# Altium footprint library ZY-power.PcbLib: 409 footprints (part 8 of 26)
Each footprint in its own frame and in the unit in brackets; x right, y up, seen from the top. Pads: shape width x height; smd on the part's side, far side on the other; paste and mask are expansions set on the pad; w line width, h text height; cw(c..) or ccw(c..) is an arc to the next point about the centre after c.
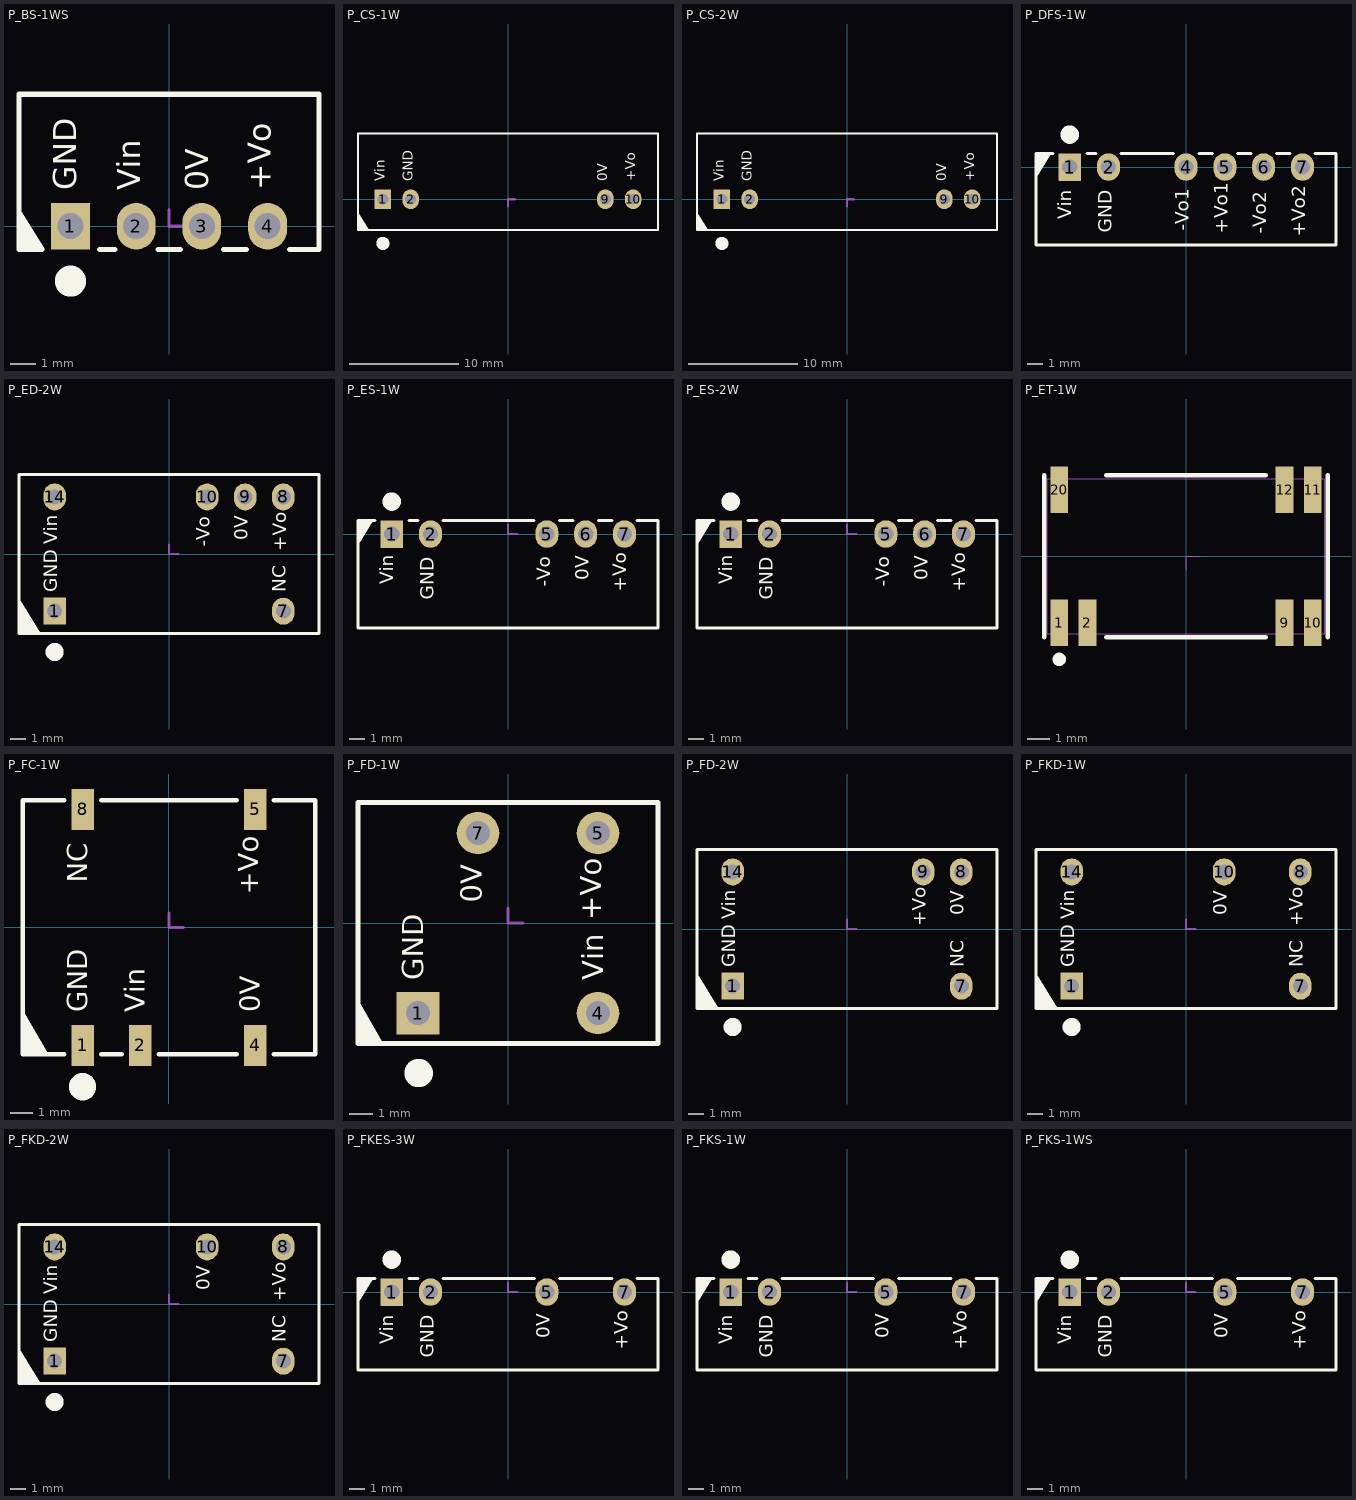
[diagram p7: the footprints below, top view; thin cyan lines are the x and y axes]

## P_BS-1WS [mm]
height 10.16
pads (4):
  rect 1.5x1.8 hole 1: 1(-3.81,0)
  oval 1.5x1.8 hole 1: 2(-1.27,0) 3(1.27,0) 4(3.81,0)
Top Overlay:
  circle w1: c-3.81,-2.125 r0.1
  region: -5.8,0.686 -5.8,-0.889 -4.813,-0.889
  lines w0.2: -4.91,-0.9 -5.8,-0.9 -5.8,5.1 5.8,5.1 5.8,-0.9 4.656,-0.9 ; -2.69,-0.9 -2.09,-0.9 ; -0.424,-0.9 0.45,-0.9 ; 2.116,-0.9 2.99,-0.9
  text "+Vo" at 4.216,1.396 h1.52
  text "0V" at 1.803,1.396 h1.52
  text "Vin" at -0.813,1.397 h1.52
  text "GND" at -3.302,1.396 h1.52
Mechanical 15:
  lines w0.127: 0,0.635 0,0 0.635,0
3D body "zhenjao01.stp": height 8.36, standoff -4.08, extent -4.51,-0.12 -3.11,1.48
3D body: height 10.16, standoff 0, extent -5.8,-0.9 5.8,5.1
3D body "zhenjao01.stp": height 8.36, standoff -4.08, extent -1.97,-0.12 -0.57,1.48
3D body "zhenjao01.stp": height 8.36, standoff -4.08, extent 0.57,-0.12 1.97,1.48
3D body "zhenjao01.stp": height 8.36, standoff -4.08, extent 3.11,-0.12 4.51,1.48

## P_CS-1W [mm]
height 11.4
pads (4):
  rect 1.5x1.8 hole 1: 1(-11.43,0)
  oval 1.5x1.8 hole 1: 2(-8.89,0) 9(8.89,0) 10(11.43,0)
Top Overlay:
  circle w1: c-11.43,-4.025 r0.1
  region: -13.7,-1.214 -13.7,-2.8 -12.706,-2.8
  lines w0.2: -13.7,-2.8 -13.7,6 13.7,6 13.7,-2.8 -13.7,-2.8
  text "+Vo" at 11.925,1.625 h1.52
  text "0V" at 9.385,1.625 h1.52
  text "GND" at -8.395,1.625 h1.52
  text "Vin" at -10.935,1.626 h1.52
Mechanical 15:
  lines w0.203: 0,-0.635 0,0 0.635,0
3D body "zhenjao01.stp": height 8.36, standoff -4.08, extent -9.59,-0.12 -8.19,1.48
3D body "zhenjao01.stp": height 8.36, standoff -4.08, extent -12.13,-0.12 -10.73,1.48
3D body "zhenjao01.stp": height 8.36, standoff -4.08, extent 8.19,-0.12 9.59,1.48
3D body "zhenjao01.stp": height 8.36, standoff -4.08, extent 10.73,-0.12 12.13,1.48
3D body: height 10.1, standoff 0, extent -13.7,-2.8 13.7,6

## P_CS-2W [mm]
height 11.5
pads (4):
  rect 1.5x1.8 hole 1: 1(-11.43,0)
  oval 1.5x1.8 hole 1: 2(-8.89,0) 9(8.89,0) 10(11.43,0)
Top Overlay:
  circle w1: c-11.43,-4.025 r0.1
  region: -13.7,-1.214 -13.7,-2.8 -12.706,-2.8
  lines w0.2: -13.7,-2.8 13.7,-2.8 13.7,6 -13.7,6 -13.7,-2.8
  text "Vin" at -10.935,1.626 h1.52
  text "GND" at -8.395,1.625 h1.52
  text "0V" at 9.385,1.625 h1.52
  text "+Vo" at 11.925,1.625 h1.52
Mechanical 15:
  lines w0.203: 0,-0.635 0,0 0.635,0
3D body "zhenjao01.stp": height 8.36, standoff -4.08, extent -9.59,-0.12 -8.19,1.48
3D body "zhenjao01.stp": height 8.36, standoff -4.08, extent -12.13,-0.12 -10.73,1.48
3D body "zhenjao01.stp": height 8.36, standoff -4.08, extent 8.19,-0.12 9.59,1.48
3D body "zhenjao01.stp": height 8.36, standoff -4.08, extent 10.73,-0.12 12.13,1.48
3D body: height 10.1, standoff 0, extent -13.7,-2.8 13.7,6

## P_DFS-1W [mm]
height 10.16
pads (6):
  rect 1.5x1.8 hole 1: 1(-7.62,0)
  oval 1.5x1.8 hole 1: 2(-5.08,0) 4(0,0) 5(2.54,0) 6(5.08,0) 7(7.62,0)
Top Overlay:
  circle w1: c-7.62,2.125 r0.1
  region: -9.83,-0.686 -9.83,0.9 -8.836,0.9
  lines w0.2: -8.72,0.9 -9.83,0.9 -9.83,-5.1 9.82,-5.1 9.82,0.9 8.44,0.9 ; -6.5,0.9 -5.9,0.9 ; -4.26,0.9 -0.82,0.9 ; 0.846,0.9 1.72,0.9 ; 3.386,0.9 4.26,0.9 ; 5.926,0.9 6.8,0.9
  text "-Vo1" at 0.478,-4.176 h1.52
  text "+Vo1" at 3.018,-4.377 h1.52
  text "-Vo2" at 5.558,-4.356 h1.52
  text "+Vo2" at 8.098,-4.556 h1.52
  text "GND" at -4.572,-4.318 h1.52
  text "Vin" at -7.239,-3.435 h1.52
Mechanical 15:
  lines w0.127: 0,0.635 0,0 0.635,0
3D body "zhenjao01.stp": height 8.36, standoff -4.08, extent 4.38,-1.48 5.78,0.12
3D body "zhenjao01.stp": height 8.36, standoff -4.08, extent -0.7,-1.48 0.7,0.12
3D body: height 10.16, standoff 0, extent -9.83,-5.1 9.82,0.9
3D body "zhenjao01.stp": height 8.36, standoff -4.08, extent 6.92,-1.48 8.32,0.12
3D body "zhenjao01.stp": height 8.36, standoff -4.08, extent 1.84,-1.48 3.24,0.12
3D body "zhenjao01.stp": height 8.36, standoff -4.08, extent -5.78,-1.48 -4.38,0.12
3D body "zhenjao01.stp": height 8.36, standoff -4.08, extent -8.32,-1.48 -6.92,0.12

## P_ED-2W [mm]
height 8.5
pads (6):
  rect 1.5x1.8 hole 1: 1(-7.62,-3.81)
  oval 1.5x1.8 hole 1: 7(7.62,-3.81) 8(7.62,3.81) 9(5.08,3.81) 10(2.54,3.81) 14(-7.62,3.81)
Top Overlay:
  circle w1: c-7.62,-6.525 r0.1
  region: -10,-2.97 -10,-5.3 -8.54,-5.3
  lines w0.2: -10,-5.3 10,-5.3 10,5.3 -10,5.3 -10,-5.3
  text "-Vo" at 3.023,0.487 h1.52
  text "+Vo" at 8.103,0.177 h1.52
  text "0V" at 5.542,0.916 h1.52
  text "GND" at -7.138,-2.557 h1.52
  text "NC" at 8.082,-2.557 h1.52
  text "Vin" at -7.138,0.645 h1.52
Mechanical 15:
  lines w0.127: 0,0.635 0,0 0.635,0
3D body: height 0, standoff -4.91, extent 2.317,3.586 2.765,4.035
3D body: height 0, standoff -4.91, extent 7.397,3.586 7.845,4.035
3D body: height 0, standoff -4.91, extent 7.397,-4.034 7.845,-3.585
3D body: height 0, standoff -4.91, extent -7.843,3.586 -7.395,4.035
3D body: height 0, standoff -4.91, extent -7.843,-4.034 -7.395,-3.585
3D body: height 8.5, standoff 0, extent -10,-5.3 10,5.3
3D body: height 0, standoff -4.91, extent 4.857,3.586 5.305,4.035

## P_ES-1W [mm]
height 10.16
pads (5):
  rect 1.5x1.8 hole 1: 1(-7.62,0)
  oval 1.5x1.8 hole 1: 2(-5.08,0) 5(2.54,0) 6(5.08,0) 7(7.62,0)
Top Overlay:
  circle w1: c-7.62,2.125 r0.1
  region: -9.83,-0.686 -9.83,0.9 -8.836,0.9
  lines w0.2: -8.72,0.9 -9.83,0.9 -9.83,-6.15 9.82,-6.15 9.82,0.9 8.44,0.9 ; -6.5,0.9 -5.9,0.9 ; -4.26,0.9 1.694,0.9 ; 3.386,0.9 4.26,0.9 ; 5.926,0.9 6.8,0.9
  text "0V" at 5.588,-3.034 h1.52
  text "Vin" at -7.239,-3.304 h1.52
  text "GND" at -4.572,-4.318 h1.52
  text "-Vo" at 3.048,-3.462 h1.52
  text "+Vo" at 8.031,-3.772 h1.52
Mechanical 15:
  lines w0.127: 0,0.635 0,0 0.635,0
3D body: height 10.1, standoff 0, extent -9.83,-6.15 9.82,0.9
3D body "zhenjao01.stp": height 8.36, standoff -4.08, extent -8.32,-1.48 -6.92,0.12
3D body "zhenjao01.stp": height 8.36, standoff -4.08, extent -5.78,-1.48 -4.38,0.12
3D body "zhenjao01.stp": height 8.36, standoff -4.08, extent 1.84,-1.48 3.24,0.12
3D body "zhenjao01.stp": height 8.36, standoff -4.08, extent 4.38,-1.48 5.78,0.12
3D body "zhenjao01.stp": height 8.36, standoff -4.08, extent 6.92,-1.48 8.32,0.12

## P_ES-2W [mm]
height 10.16
pads (5):
  rect 1.5x1.8 hole 1: 1(-7.62,0)
  oval 1.5x1.8 hole 1: 2(-5.08,0) 5(2.54,0) 6(5.08,0) 7(7.62,0)
Top Overlay:
  circle w1: c-7.62,2.125 r0.1
  region: -9.83,-0.686 -9.83,0.9 -8.836,0.9
  lines w0.2: -8.72,0.9 -9.83,0.9 -9.83,-6.15 9.82,-6.15 9.82,0.9 8.44,0.9 ; -6.5,0.9 -5.9,0.9 ; -4.26,0.9 1.694,0.9 ; 3.386,0.9 4.26,0.9 ; 5.926,0.9 6.8,0.9
  text "+Vo" at 8.031,-3.772 h1.52
  text "-Vo" at 3.048,-3.462 h1.52
  text "GND" at -4.572,-4.318 h1.52
  text "Vin" at -7.239,-3.304 h1.52
  text "0V" at 5.588,-3.034 h1.52
Mechanical 15:
  lines w0.127: 0,0.635 0,0 0.635,0
3D body "zhenjao01.stp": height 8.36, standoff -4.08, extent 6.92,-1.48 8.32,0.12
3D body "zhenjao01.stp": height 8.36, standoff -4.08, extent 4.38,-1.48 5.78,0.12
3D body "zhenjao01.stp": height 8.36, standoff -4.08, extent 1.84,-1.48 3.24,0.12
3D body "zhenjao01.stp": height 8.36, standoff -4.08, extent -5.78,-1.48 -4.38,0.12
3D body "zhenjao01.stp": height 8.36, standoff -4.08, extent -8.32,-1.48 -6.92,0.12
3D body: height 10.1, standoff 0, extent -9.83,-6.15 9.82,0.9

## P_ET-1W [mm]
height 3
pads (7):
  rect 0.8x2.1 smd: 1(-5.715,-3) 2(-4.445,-3) 9(4.445,-3) 10(5.715,-3) 11(5.715,3) 12(4.445,3) 20(-5.715,3)
Top Overlay:
  circle w0.4: c-5.715,-4.649 r0.1
  lines w0.2: -6.4,-3.65 -6.4,3.65 ; -3.6,-3.65 3.6,-3.65 ; -3.6,3.65 3.6,3.65 ; 6.4,-3.65 6.4,3.65
Mechanical 13:
  lines w0.05: -6.25,-3.5 6.25,-3.5 6.25,3.5 -6.25,3.5 -6.25,-3.5
Mechanical 15:
  lines w0.05: 0,-0.635 0,0 0.635,0

## P_FC-1W [mm]
height 7.14
pads (5):
  rect 1x1.8 smd: 1(-3.81,-5.203) 2(-1.27,-5.203) 4(3.81,-5.203) 5(3.81,5.203) 8(-3.81,5.203)
Top Overlay:
  circle w1: c-3.812,-7.026 r0.1
  region: -5.334,-5.6 -6.45,-3.661 -6.45,-5.6
  lines w0.2: -4.623,-5.6 -6.45,-5.6 -6.45,5.6 -4.623,5.6 ; -2.997,-5.6 -2.084,-5.6 ; -2.997,5.6 2.997,5.6 ; -0.456,-5.6 2.997,-5.6 ; 4.623,-5.6 6.45,-5.6 6.45,5.6 4.623,5.6
  text "NC" at -3.302,1.972 h1.52
  text "Vin" at -0.762,-3.739 h1.52
  text "+Vo" at 4.244,1.443 h1.52
  text "0V" at 4.318,-3.741 h1.52
  text "GND" at -3.302,-3.741 h1.52
Mechanical 15:
  lines w0.127: 0,0.635 0,0 0.635,0

## P_FD-1W [mm]
height 8.1
pads (4):
  rect 1.8x1.8 hole 1: 1(-3.81,-3.81)
  round 1.8 hole 1: 4(3.81,-3.81) 5(3.81,3.81) 7(-1.27,3.81)
Top Overlay:
  circle w1: c-3.783,-6.35 r0.1
  region: -5.234,-5.2 -6.35,-3.261 -6.35,-5.2
  lines w0.2: -6.35,-5.1 6.35,-5.1 6.35,5.1 -6.35,5.1 -6.35,-5.1
  text "GND" at -3.302,-2.413 h1.52
  text "Vin" at 4.318,-2.413 h1.52
  text "+Vo" at 4.244,0.127 h1.52
  text "0V" at -0.813,0.864 h1.52
Mechanical 15:
  lines w0.127: 0,0.635 0,0 0.635,0
3D body: height 0, standoff -4.91, extent -4.033,-4.034 -3.585,-3.585
3D body: height 0, standoff -4.91, extent 3.587,-4.034 4.035,-3.585
3D body: height 0, standoff -4.91, extent 3.587,3.586 4.035,4.035
3D body: height 0, standoff -4.91, extent -1.493,3.586 -1.045,4.035
3D body: height 8.1, standoff 0, extent -6.35,-5.1 6.35,5.1

## P_FD-2W [mm]
height 8.5
pads (5):
  rect 1.5x1.8 hole 1: 1(-7.62,-3.81)
  oval 1.5x1.8 hole 1: 7(7.62,-3.81) 8(7.62,3.81) 9(5.08,3.81) 14(-7.62,3.81)
Top Overlay:
  circle w1: c-7.62,-6.525 r0.1
  region: -10,-2.97 -10,-5.3 -8.54,-5.3
  lines w0.2: -10,-5.3 -10,5.3 10,5.3 10,-5.3 -10,-5.3
  text "0V" at 8.082,0.916 h1.52
  text "+Vo" at 5.563,0.177 h1.52
  text "Vin" at -7.138,0.645 h1.52
  text "NC" at 8.082,-2.557 h1.52
  text "GND" at -7.138,-2.557 h1.52
Mechanical 15:
  lines w0.127: 0,0.635 0,0 0.635,0
3D body: height 0, standoff -4.91, extent 4.857,3.586 5.305,4.035
3D body: height 8.5, standoff 0, extent -10,-5.3 10,5.3
3D body: height 0, standoff -4.91, extent -7.843,-4.034 -7.395,-3.585
3D body: height 0, standoff -4.91, extent -7.843,3.586 -7.395,4.035
3D body: height 0, standoff -4.91, extent 7.397,-4.034 7.845,-3.585
3D body: height 0, standoff -4.91, extent 7.397,3.586 7.845,4.035

## P_FKD-1W [mm]
height 8.5
pads (5):
  rect 1.5x1.8 hole 1: 1(-7.62,-3.81)
  oval 1.5x1.8 hole 1: 7(7.62,-3.81) 8(7.62,3.81) 10(2.54,3.81) 14(-7.62,3.81)
Top Overlay:
  circle w1: c-7.62,-6.525 r0.1
  region: -10,-2.97 -10,-5.3 -8.54,-5.3
  lines w0.2: -10,-5.3 10,-5.3 10,5.3 -10,5.3 -10,-5.3
  text "GND" at -7.138,-2.557 h1.52
  text "NC" at 8.082,-2.557 h1.52
  text "Vin" at -7.138,0.645 h1.52
  text "+Vo" at 8.082,0.177 h1.52
  text "0V" at 3.002,0.916 h1.52
Mechanical 15:
  lines w0.127: 0,0.635 0,0 0.635,0
3D body: height 0, standoff -4.91, extent 2.317,3.586 2.765,4.035
3D body: height 0, standoff -4.91, extent 7.397,3.586 7.845,4.035
3D body: height 0, standoff -4.91, extent 7.397,-4.034 7.845,-3.585
3D body: height 0, standoff -4.91, extent -7.843,3.586 -7.395,4.035
3D body: height 0, standoff -4.91, extent -7.843,-4.034 -7.395,-3.585
3D body: height 8.5, standoff 0, extent -10,-5.3 10,5.3

## P_FKD-2W [mm]
height 8.5
pads (5):
  rect 1.5x1.8 hole 1: 1(-7.62,-3.81)
  oval 1.5x1.8 hole 1: 7(7.62,-3.81) 8(7.62,3.81) 10(2.54,3.81) 14(-7.62,3.81)
Top Overlay:
  circle w1: c-7.62,-6.525 r0.1
  region: -10,-2.97 -10,-5.3 -8.54,-5.3
  lines w0.2: -10,-5.3 10,-5.3 10,5.3 -10,5.3 -10,-5.3
  text "GND" at -7.138,-2.557 h1.52
  text "NC" at 8.082,-2.557 h1.52
  text "Vin" at -7.138,0.645 h1.52
  text "+Vo" at 8.082,0.177 h1.52
  text "0V" at 3.002,0.916 h1.52
Mechanical 15:
  lines w0.127: 0,0.635 0,0 0.635,0
3D body: height 0, standoff -4.91, extent 2.317,3.586 2.765,4.035
3D body: height 0, standoff -4.91, extent 7.397,3.586 7.845,4.035
3D body: height 0, standoff -4.91, extent 7.397,-4.034 7.845,-3.585
3D body: height 0, standoff -4.91, extent -7.843,3.586 -7.395,4.035
3D body: height 0, standoff -4.91, extent -7.843,-4.034 -7.395,-3.585
3D body: height 8.5, standoff 0, extent -10,-5.3 10,5.3

## P_FKES-3W [mm]
height 10.16
pads (4):
  rect 1.5x1.8 hole 1: 1(-7.62,0)
  oval 1.5x1.8 hole 1: 2(-5.08,0) 5(2.54,0) 7(7.62,0)
Top Overlay:
  circle w1: c-7.62,2.125 r0.1
  region: -9.83,-0.686 -9.83,0.9 -8.836,0.9
  lines w0.2: -8.72,0.9 -9.83,0.9 -9.83,-5.1 9.82,-5.1 9.82,0.9 8.44,0.9 ; -6.5,0.9 -5.9,0.9 ; -4.26,0.9 1.72,0.9 ; 3.36,0.9 6.8,0.9
  text "+Vo" at 8.128,-3.776 h1.52
  text "0V" at 3.021,-3.036 h1.52
  text "GND" at -4.572,-4.318 h1.52
  text "Vin" at -7.239,-3.435 h1.52
Mechanical 15:
  lines w0.127: 0,0.635 0,0 0.635,0
3D body: height 10.16, standoff 0, extent -9.83,-5.1 9.82,0.9
3D body "zhenjao01.stp": height 8.36, standoff -4.08, extent 6.92,-1.48 8.32,0.12
3D body "zhenjao01.stp": height 8.36, standoff -4.08, extent 1.84,-1.48 3.24,0.12
3D body "zhenjao01.stp": height 8.36, standoff -4.08, extent -5.78,-1.48 -4.38,0.12
3D body "zhenjao01.stp": height 8.36, standoff -4.08, extent -8.32,-1.48 -6.92,0.12

## P_FKS-1W [mm]
height 10.16
pads (4):
  rect 1.5x1.8 hole 1: 1(-7.62,0)
  oval 1.5x1.8 hole 1: 2(-5.08,0) 5(2.54,0) 7(7.62,0)
Top Overlay:
  circle w1: c-7.62,2.125 r0.1
  region: -9.83,-0.686 -9.83,0.9 -8.836,0.9
  lines w0.2: -8.72,0.9 -9.83,0.9 -9.83,-5.1 9.82,-5.1 9.82,0.9 8.44,0.9 ; -6.5,0.9 -5.9,0.9 ; -4.26,0.9 1.72,0.9 ; 3.36,0.9 6.8,0.9
  text "+Vo" at 8.128,-3.776 h1.52
  text "0V" at 3.021,-3.036 h1.52
  text "GND" at -4.572,-4.318 h1.52
  text "Vin" at -7.239,-3.435 h1.52
Mechanical 15:
  lines w0.127: 0,0.635 0,0 0.635,0
3D body: height 10.16, standoff 0, extent -9.83,-5.1 9.82,0.9
3D body "zhenjao01.stp": height 8.36, standoff -4.08, extent 6.92,-1.48 8.32,0.12
3D body "zhenjao01.stp": height 8.36, standoff -4.08, extent 1.84,-1.48 3.24,0.12
3D body "zhenjao01.stp": height 8.36, standoff -4.08, extent -5.78,-1.48 -4.38,0.12
3D body "zhenjao01.stp": height 8.36, standoff -4.08, extent -8.32,-1.48 -6.92,0.12

## P_FKS-1WS [mm]
height 10.16
pads (4):
  rect 1.5x1.8 hole 1: 1(-7.62,0)
  oval 1.5x1.8 hole 1: 2(-5.08,0) 5(2.54,0) 7(7.62,0)
Top Overlay:
  circle w1: c-7.62,2.125 r0.1
  region: -9.83,-0.686 -9.83,0.9 -8.836,0.9
  lines w0.2: -8.72,0.9 -9.83,0.9 -9.83,-5.1 9.82,-5.1 9.82,0.9 8.44,0.9 ; -6.5,0.9 -5.9,0.9 ; -4.26,0.9 1.72,0.9 ; 3.36,0.9 6.8,0.9
  text "+Vo" at 8.128,-3.776 h1.52
  text "0V" at 3.021,-3.036 h1.52
  text "GND" at -4.572,-4.318 h1.52
  text "Vin" at -7.239,-3.435 h1.52
Mechanical 15:
  lines w0.127: 0,0.635 0,0 0.635,0
3D body: height 10.16, standoff 0, extent -9.83,-5.1 9.82,0.9
3D body "zhenjao01.stp": height 8.36, standoff -4.08, extent 6.92,-1.48 8.32,0.12
3D body "zhenjao01.stp": height 8.36, standoff -4.08, extent 1.84,-1.48 3.24,0.12
3D body "zhenjao01.stp": height 8.36, standoff -4.08, extent -5.78,-1.48 -4.38,0.12
3D body "zhenjao01.stp": height 8.36, standoff -4.08, extent -8.32,-1.48 -6.92,0.12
